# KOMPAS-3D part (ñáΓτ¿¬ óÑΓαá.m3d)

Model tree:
1. Эскиз:1
2. Операция выдавливания:1
     Расстояние 1 = 4; Расстояние 2 = 25
3. Эскиз:2
4. Операция выдавливания:2
     Расстояние 1 = 4; Угол 1 = 8; Расстояние 2 = 3; Угол 2 = 6
5. Эскиз:3
6. Операция выдавливания:3
     Расстояние 1 = 4.4; Расстояние 2 = 3; Угол 2 = 6
7. Эскиз:4
8. Операция выдавливания:4
     Расстояние 1 = 4.4; Расстояние 2 = 1
9. Эскиз:5
10. Операция выдавливания:5
     Расстояние 1 = 4.4; Расстояние 2 = 1
11. Эскиз:6
12. Вырезать элемент выдавливания:2
     Расстояние 1 = 4.4
13. Эскиз:7
14. Вырезать элемент выдавливания:3
     Расстояние 1 = 2
15. Эскиз:8
16. Операция выдавливания:6
     Расстояние 1 = 5; Расстояние 2 = 1
17. Эскиз:9
18. Операция выдавливания:7
     Расстояние 1 = 3; Угол 1 = 10; Расстояние 2 = 1
19. Эскиз:10
20. Вырезать элемент выдавливания:4
     Расстояние 1 = 3
21. Эскиз:11
22. Вырезать элемент выдавливания:5
     Расстояние 1 = 3
23. Эскиз:12
24. Операция выдавливания:8
     Расстояние 1 = 4; Расстояние 2 = 1
25. Эскиз:13
26. Вырезать элемент выдавливания:6
     Расстояние 1 = 2
27. Эскиз:14
28. Операция выдавливания:9
     Расстояние 1 = 1; Расстояние 2 = 1
29. Эскиз:15
30. Операция выдавливания:10
     Расстояние 1 = 3; Угол 1 = 16; Расстояние 2 = 1
31. Эскиз:16
32. Операция выдавливания:11
     Расстояние 1 = 2; Расстояние 2 = 1
33. Эскиз:17
34. Операция выдавливания:12
     Расстояние 1 = 4; Расстояние 2 = 1
35. Эскиз:18
36. Операция выдавливания:13
     Расстояние 1 = 4; Расстояние 2 = 2
37. Эскиз:19
38. Операция выдавливания:14
     Расстояние 1 = 4; Расстояние 2 = 2

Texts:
  stalker61
  Сплав АЛ8  ГОСТ 1583-93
